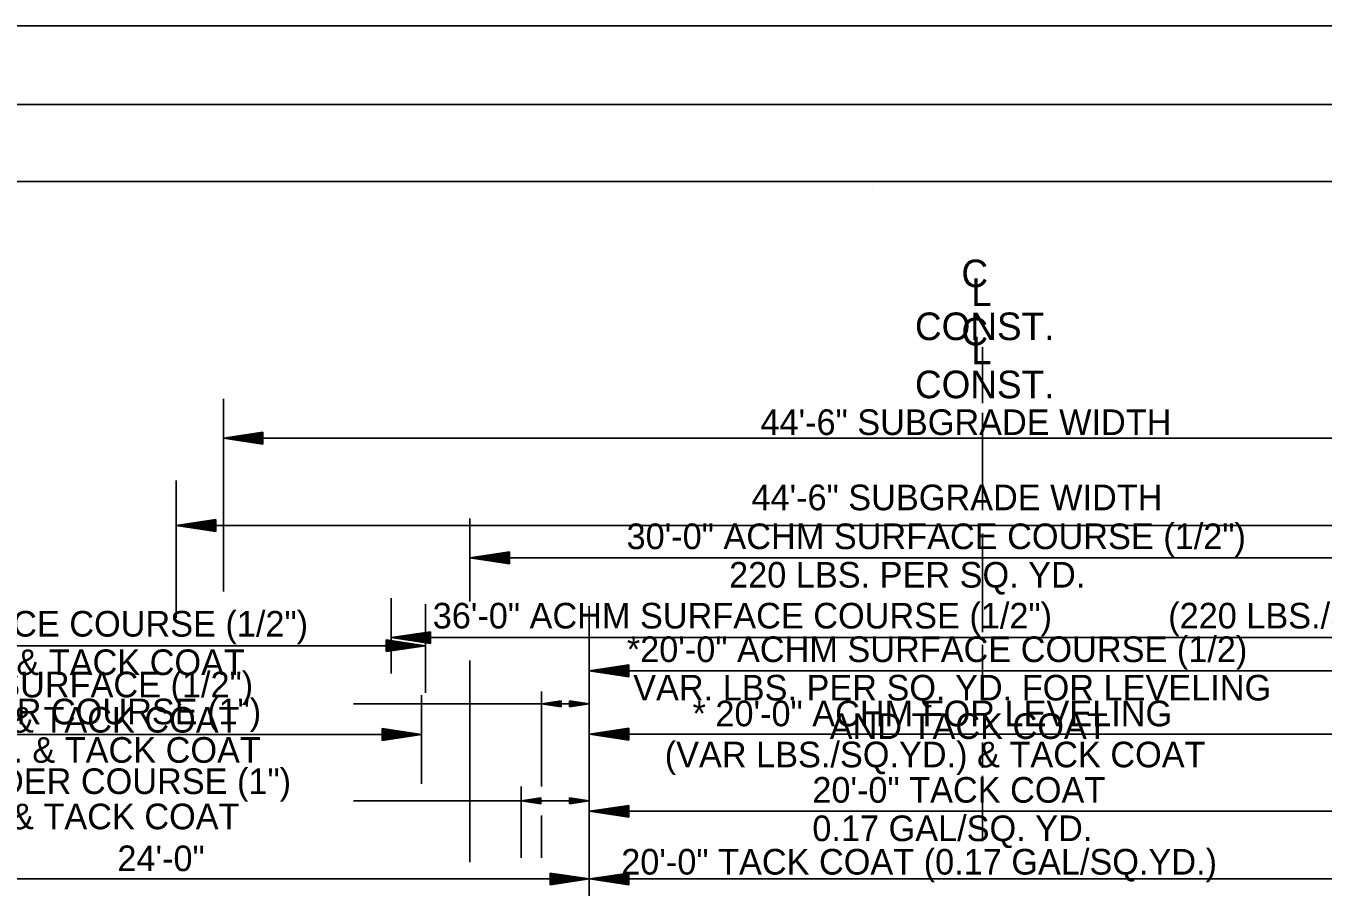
# Model space of a CAD drawing. Extents: x 1373719 to 1374161, y 379835 to 380167.
# Drawn here: x 1373940.76 to 1373973.66, y 380119.8 to 380141.63 of the extents above; entities that cross this region are included whole.
import ezdxf

# ---------------------------------------------------------------- set-up
doc = ezdxf.new("R2010")
doc.units = 0
for name, color, linetype in [('CL Construction', 7, 'Continuous'), ('DATE', 7, 'Continuous'), ('GREEN_TXT', 7, 'Continuous'), ('R_NoPlot', 7, 'Continuous'), ('Text 1', 7, 'Continuous')]:
    doc.layers.add(name, color=color, linetype=linetype)

msp = doc.modelspace()

# ---------------------------------------------------------------- linework, layer by layer
at = {"layer": 'CL Construction'}
for p, q in [((1373965.018, 380130.103), (1373965.018, 380131.819)), ((1373965.018, 380127.222), (1373965.018, 380128.764)), ((1373965.018, 380124.762), (1373965.018, 380125.938)), ((1373965.018, 380120.955), (1373965.018, 380122.619))]:
    msp.add_line(p, q, dxfattribs=at)
at = {"layer": 'DATE'}
for p, q in [((1374046.363, 380141.63), (1373870.363, 380141.63)), ((1373885.973, 380137.69), (1374044.063, 380137.69)), ((1373962.233, 380137.56), (1373962.233, 380137.56)), ((1373962.233, 380137.56), (1373962.233, 380137.56))]:
    msp.add_line(p, q, dxfattribs=at)
at = {"layer": 'GREEN_TXT'}
for p, q in [((1373944.572, 380130.103), (1373944.572, 380126.626)), ((1373945.572, 380129.112), (1373944.572, 380128.962)), ((1373985.467, 380128.962), (1373944.572, 380128.962)), ((1373945.572, 380128.812), (1373944.572, 380128.962)), ((1373945.572, 380129.087), (1373944.739, 380128.962)), ((1373945.572, 380128.837), (1373944.739, 380128.962)), ((1373945.572, 380129.062), (1373944.911, 380128.962)), ((1373945.572, 380128.863), (1373944.911, 380128.962)), ((1373945.572, 380129.037), (1373945.078, 380128.962)), ((1373945.572, 380128.888), (1373945.078, 380128.962)), ((1373945.572, 380129.011), (1373945.247, 380128.962)), ((1373945.572, 380128.914), (1373945.247, 380128.962)), ((1373945.572, 380128.986), (1373945.414, 380128.962)), ((1373945.572, 380128.939), (1373945.414, 380128.962)), ((1373945.572, 380128.812), (1373945.572, 380129.112)), ((1373950.02, 380127.121), (1373950.02, 380125.214)), ((1373951.02, 380126.271), (1373950.02, 380126.121)), ((1373951.02, 380126.246), (1373950.187, 380126.121)), ((1373951.02, 380126.22), (1373950.359, 380126.121)), ((1373951.02, 380126.195), (1373950.525, 380126.121)), ((1373951.02, 380126.17), (1373950.695, 380126.121)), ((1373951.02, 380125.971), (1373951.02, 380126.271)), ((1373980.02, 380126.121), (1373950.02, 380126.121)), ((1373951.02, 380125.971), (1373950.02, 380126.121)), ((1373951.02, 380125.996), (1373950.187, 380126.121)), ((1373951.02, 380126.021), (1373950.359, 380126.121)), ((1373951.02, 380126.046), (1373950.525, 380126.121)), ((1373951.02, 380126.072), (1373950.695, 380126.121)), ((1373951.02, 380126.144), (1373950.862, 380126.121)), ((1373951.02, 380126.097), (1373950.862, 380126.121)), ((1373953.833, 380122.346), (1373953.833, 380124.751)), ((1373954.333, 380124.517), (1373953.833, 380124.442)), ((1373954.333, 380124.367), (1373954.333, 380124.517)), ((1373954.544, 380124.517), (1373955.044, 380124.442)), ((1373954.544, 380124.517), (1373954.544, 380124.367)), ((1373955.044, 380122.166), (1373955.044, 380124.751)), ((1373953.833, 380124.442), (1373955.044, 380124.442)), ((1373954.333, 380124.367), (1373953.833, 380124.442)), ((1373954.333, 380124.504), (1373953.917, 380124.442)), ((1373954.333, 380124.379), (1373953.917, 380124.442)), ((1373954.333, 380124.491), (1373954.003, 380124.442)), ((1373954.333, 380124.392), (1373954.003, 380124.442)), ((1373954.333, 380124.479), (1373954.086, 380124.442)), ((1373954.333, 380124.404), (1373954.086, 380124.442)), ((1373954.333, 380124.466), (1373954.171, 380124.442)), ((1373954.333, 380124.417), (1373954.171, 380124.442)), ((1373954.333, 380124.453), (1373954.254, 380124.442)), ((1373954.333, 380124.43), (1373954.254, 380124.442)), ((1373954.544, 380124.504), (1373954.961, 380124.442)), ((1373954.544, 380124.491), (1373954.875, 380124.442)), ((1373954.544, 380124.479), (1373954.792, 380124.442)), ((1373954.544, 380124.466), (1373954.707, 380124.442)), ((1373954.544, 380124.453), (1373954.623, 380124.442)), ((1373954.544, 380124.367), (1373955.044, 380124.442)), ((1373954.544, 380124.417), (1373954.707, 380124.442)), ((1373954.544, 380124.392), (1373954.875, 380124.442)), ((1373954.544, 380124.379), (1373954.961, 380124.442)), ((1373954.544, 380124.404), (1373954.792, 380124.442)), ((1373954.544, 380124.43), (1373954.623, 380124.442)), ((1373956.05, 380123.824), (1373955.05, 380123.674)), ((1373955.05, 380123.674), (1373975.044, 380123.674)), ((1373956.05, 380123.524), (1373955.05, 380123.674)), ((1373956.05, 380123.799), (1373955.217, 380123.674)), ((1373956.05, 380123.549), (1373955.217, 380123.674)), ((1373956.05, 380123.774), (1373955.389, 380123.674)), ((1373956.05, 380123.575), (1373955.389, 380123.674)), ((1373956.05, 380123.749), (1373955.556, 380123.674)), ((1373956.05, 380123.6), (1373955.556, 380123.674)), ((1373956.05, 380123.723), (1373955.725, 380123.674)), ((1373956.05, 380123.626), (1373955.725, 380123.674)), ((1373956.05, 380123.698), (1373955.892, 380123.674)), ((1373956.05, 380123.651), (1373955.892, 380123.674)), ((1373956.05, 380123.524), (1373956.05, 380123.824)), ((1373953.319, 380120.537), (1373953.319, 380122.346)), ((1373953.819, 380122.055), (1373953.319, 380121.98)), ((1373953.319, 380121.98), (1373955.044, 380121.98)), ((1373953.819, 380121.905), (1373953.319, 380121.98)), ((1373953.819, 380122.042), (1373953.402, 380121.98)), ((1373953.819, 380121.917), (1373953.402, 380121.98)), ((1373953.819, 380122.029), (1373953.488, 380121.98)), ((1373953.819, 380121.93), (1373953.488, 380121.98)), ((1373953.819, 380122.017), (1373953.572, 380121.98)), ((1373953.819, 380121.942), (1373953.572, 380121.98)), ((1373953.819, 380122.004), (1373953.656, 380121.98)), ((1373953.819, 380121.955), (1373953.656, 380121.98)), ((1373953.819, 380121.991), (1373953.74, 380121.98)), ((1373953.819, 380121.968), (1373953.74, 380121.98)), ((1373953.819, 380121.905), (1373953.819, 380122.055)), ((1373954.544, 380122.055), (1373955.044, 380121.98)), ((1373954.544, 380122.055), (1373954.544, 380121.905)), ((1373954.544, 380122.042), (1373954.961, 380121.98)), ((1373954.544, 380122.029), (1373954.875, 380121.98)), ((1373954.544, 380122.017), (1373954.792, 380121.98)), ((1373954.544, 380122.004), (1373954.707, 380121.98)), ((1373954.544, 380121.991), (1373954.623, 380121.98)), ((1373954.544, 380121.905), (1373955.044, 380121.98)), ((1373954.544, 380121.955), (1373954.707, 380121.98)), ((1373954.544, 380121.93), (1373954.875, 380121.98)), ((1373954.544, 380121.917), (1373954.961, 380121.98)), ((1373954.544, 380121.942), (1373954.792, 380121.98)), ((1373954.544, 380121.968), (1373954.623, 380121.98)), ((1373955.044, 380118.359), (1373955.044, 380122.166)), ((1373953.833, 380120.537), (1373953.833, 380121.61)), ((1373934.02, 380120.001), (1373955.05, 380120.001)), ((1373954.05, 380120.151), (1373955.05, 380120.001)), ((1373954.05, 380120.151), (1373954.05, 380119.851)), ((1373954.05, 380120.126), (1373954.883, 380120.001)), ((1373954.05, 380120.101), (1373954.711, 380120.001)), ((1373954.05, 380120.076), (1373954.545, 380120.001)), ((1373954.05, 380120.05), (1373954.375, 380120.001)), ((1373954.05, 380120.025), (1373954.208, 380120.001)), ((1373954.05, 380119.851), (1373955.05, 380120.001)), ((1373954.05, 380119.952), (1373954.375, 380120.001)), ((1373954.05, 380119.902), (1373954.711, 380120.001)), ((1373954.05, 380119.876), (1373954.883, 380120.001)), ((1373954.05, 380119.927), (1373954.545, 380120.001)), ((1373954.05, 380119.978), (1373954.208, 380120.001)), ((1373956.05, 380120.151), (1373955.05, 380120.001)), ((1373955.05, 380120.001), (1373975.044, 380120.001)), ((1373956.05, 380119.851), (1373955.05, 380120.001)), ((1373956.05, 380120.126), (1373955.217, 380120.001)), ((1373956.05, 380119.876), (1373955.217, 380120.001)), ((1373956.05, 380120.101), (1373955.389, 380120.001)), ((1373956.05, 380119.902), (1373955.389, 380120.001)), ((1373956.05, 380120.076), (1373955.556, 380120.001)), ((1373956.05, 380119.927), (1373955.556, 380120.001)), ((1373956.05, 380120.05), (1373955.725, 380120.001)), ((1373956.05, 380119.953), (1373955.725, 380120.001)), ((1373956.05, 380120.025), (1373955.892, 380120.001)), ((1373956.05, 380119.978), (1373955.892, 380120.001)), ((1373956.05, 380119.851), (1373956.05, 380120.151))]:
    msp.add_line(p, q, dxfattribs=at)
for points in [[(1373949.063, 380124.442), (1373953.833, 380124.442)], [(1373949.063, 380121.98), (1373953.319, 380121.98)]]:
    msp.add_lwpolyline(points, dxfattribs=at)
at = {"layer": 'R_NoPlot'}
msp.add_lwpolyline([(1373879.769, 380139.637), (1374046.439, 380139.637), (1374046.439, 380032.969), (1373879.769, 380032.969)], close=True, dxfattribs=at)
at = {"layer": 'Text 1'}
for p, q in [((1373965.018, 380132.064), (1373965.018, 380133.484)), ((1373945.768, 380127.292), (1373945.768, 380132.177)), ((1373946.768, 380131.327), (1373945.768, 380131.177)), ((1373945.768, 380131.177), (1373984.268, 380131.177)), ((1373946.768, 380131.027), (1373945.768, 380131.177)), ((1373946.768, 380131.302), (1373945.935, 380131.177)), ((1373946.768, 380131.052), (1373945.935, 380131.177)), ((1373946.768, 380131.276), (1373946.107, 380131.177)), ((1373946.768, 380131.077), (1373946.107, 380131.177)), ((1373946.768, 380131.251), (1373946.273, 380131.177)), ((1373946.768, 380131.102), (1373946.273, 380131.177)), ((1373946.768, 380131.226), (1373946.443, 380131.177)), ((1373946.768, 380131.128), (1373946.443, 380131.177)), ((1373946.768, 380131.2), (1373946.61, 380131.177)), ((1373946.768, 380131.153), (1373946.61, 380131.177)), ((1373946.768, 380131.027), (1373946.768, 380131.327)), ((1373965.018, 380129.348), (1373965.018, 380130.891)), ((1373952.02, 380129.144), (1373952.02, 380127.032)), ((1373953.018, 380128.294), (1373952.018, 380128.144)), ((1373953.018, 380127.994), (1373952.018, 380128.144)), ((1373952.02, 380128.144), (1373978.02, 380128.144)), ((1373953.018, 380128.269), (1373952.185, 380128.144)), ((1373953.018, 380128.019), (1373952.185, 380128.144)), ((1373953.018, 380128.244), (1373952.357, 380128.144)), ((1373953.018, 380128.045), (1373952.357, 380128.144)), ((1373953.018, 380128.219), (1373952.524, 380128.144)), ((1373953.018, 380128.07), (1373952.524, 380128.144)), ((1373953.018, 380128.193), (1373952.693, 380128.144)), ((1373953.018, 380128.096), (1373952.693, 380128.144)), ((1373953.018, 380128.168), (1373952.86, 380128.144)), ((1373953.018, 380128.121), (1373952.86, 380128.144)), ((1373953.018, 380127.994), (1373953.018, 380128.294)), ((1373965.018, 380126.962), (1373965.018, 380127.293)), ((1373950.895, 380124.718), (1373950.895, 380126.972)), ((1373955.044, 380118.358), (1373955.044, 380126.916)), ((1373965.018, 380126.259), (1373965.018, 380126.962)), ((1373950.895, 380125.916), (1373930.823, 380125.916)), ((1373949.895, 380126.066), (1373950.895, 380125.916)), ((1373949.895, 380126.066), (1373949.895, 380125.766)), ((1373949.895, 380126.041), (1373950.728, 380125.916)), ((1373949.895, 380126.015), (1373950.556, 380125.916)), ((1373949.895, 380125.99), (1373950.389, 380125.916)), ((1373949.895, 380125.964), (1373950.22, 380125.916)), ((1373949.895, 380125.939), (1373950.053, 380125.916)), ((1373949.895, 380125.766), (1373950.895, 380125.916)), ((1373949.895, 380125.867), (1373950.22, 380125.916)), ((1373949.895, 380125.816), (1373950.556, 380125.916)), ((1373949.895, 380125.791), (1373950.728, 380125.916)), ((1373949.895, 380125.841), (1373950.389, 380125.916)), ((1373949.895, 380125.892), (1373950.053, 380125.916)), ((1373952.02, 380125.538), (1373952.02, 380120.424)), ((1373956.046, 380125.429), (1373955.046, 380125.279)), ((1373956.046, 380125.129), (1373955.046, 380125.279)), ((1373955.046, 380125.279), (1373975.044, 380125.279)), ((1373956.046, 380125.404), (1373955.213, 380125.279)), ((1373956.046, 380125.154), (1373955.213, 380125.279)), ((1373956.046, 380125.378), (1373955.385, 380125.279)), ((1373956.046, 380125.179), (1373955.385, 380125.279)), ((1373956.046, 380125.353), (1373955.551, 380125.279)), ((1373956.046, 380125.204), (1373955.551, 380125.279)), ((1373956.046, 380125.328), (1373955.721, 380125.279)), ((1373956.046, 380125.23), (1373955.721, 380125.279)), ((1373956.046, 380125.302), (1373955.888, 380125.279)), ((1373956.046, 380125.255), (1373955.888, 380125.279)), ((1373956.046, 380125.129), (1373956.046, 380125.429)), ((1373950.79, 380122.412), (1373950.79, 380124.665)), ((1373950.79, 380123.665), (1373930.823, 380123.665)), ((1373949.79, 380123.815), (1373950.79, 380123.665)), ((1373949.79, 380123.815), (1373949.79, 380123.515)), ((1373949.79, 380123.79), (1373950.623, 380123.665)), ((1373949.79, 380123.765), (1373950.451, 380123.665)), ((1373949.79, 380123.74), (1373950.284, 380123.665)), ((1373949.79, 380123.714), (1373950.115, 380123.665)), ((1373949.79, 380123.689), (1373949.948, 380123.665)), ((1373949.79, 380123.515), (1373950.79, 380123.665)), ((1373949.79, 380123.616), (1373950.115, 380123.665)), ((1373949.79, 380123.566), (1373950.451, 380123.665)), ((1373949.79, 380123.54), (1373950.623, 380123.665)), ((1373949.79, 380123.591), (1373950.284, 380123.665)), ((1373949.79, 380123.642), (1373949.948, 380123.665)), ((1373965.018, 380122.821), (1373965.018, 380123.461)), ((1373975.044, 380121.718), (1373955.044, 380121.718)), ((1373956.048, 380121.866), (1373955.048, 380121.716)), ((1373956.048, 380121.566), (1373955.048, 380121.716)), ((1373956.048, 380121.841), (1373955.215, 380121.716)), ((1373956.048, 380121.591), (1373955.215, 380121.716)), ((1373956.048, 380121.816), (1373955.387, 380121.716)), ((1373956.048, 380121.617), (1373955.387, 380121.716)), ((1373956.048, 380121.791), (1373955.554, 380121.716)), ((1373956.048, 380121.642), (1373955.554, 380121.716)), ((1373956.048, 380121.765), (1373955.723, 380121.716)), ((1373956.048, 380121.668), (1373955.723, 380121.716)), ((1373956.048, 380121.74), (1373955.89, 380121.716)), ((1373956.048, 380121.693), (1373955.89, 380121.716)), ((1373956.048, 380121.566), (1373956.048, 380121.866))]:
    msp.add_line(p, q, dxfattribs=at)

# ---------------------------------------------------------------- texts
at = {"layer": 'CL Construction'}
for s, p in [('C', (1373964.484, 380133.531)), ('L', (1373964.731, 380133.054)), ('CONST.', (1373963.306, 380132.19))]:
    msp.add_text(s, height=0.7, dxfattribs=at).set_placement(p)
at = {"layer": 'GREEN_TXT'}
for s, p in [('44\'-6" SUBGRADE WIDTH', (1373959.159, 380129.35)), ('36\'-0" ACHM SURFACE COURSE (1/2") ', (1373951.075, 380126.352)), ('(220 LBS./SQ. YD.)', (1373969.728, 380126.352)), ('2\'-1 1/2" ACHM SURFACE (1/2")', (1373933.807, 380124.606)), ('* 20\'-0" ACHM FOR LEVELING', (1373957.665, 380123.872)), ('(220 LBS./SQ. YD.) & TACK COAT', (1373932.555, 380123.712)), ('(VAR LBS./SQ.YD.) & TACK COAT', (1373956.959, 380122.832)), ('2\'-2 3/4" ACHM BINDER COURSE (1")', (1373932.403, 380122.155)), ('(330 LBS./SQ. YD.) & TACK COAT', (1373932.554, 380121.261)), ('24\'-0"', (1373943.077, 380120.199)), ('20\'-0" TACK COAT (0.17 GAL/SQ.YD.)', (1373955.856, 380120.112))]:
    msp.add_text(s, height=0.65, dxfattribs=at).set_placement(p)
at = {"layer": 'Text 1'}
for s, height, p in [('C', 0.7, (1373964.484, 380135.006)), ('L', 0.7, (1373964.731, 380134.528)), ('CONST.', 0.7, (1373963.306, 380133.664)), ('44\'-6" SUBGRADE WIDTH', 0.65, (1373959.387, 380131.258)), ('30\'-0" ACHM SURFACE COURSE (1/2")', 0.65, (1373955.992, 380128.364)), ('220 LBS. PER SQ. YD.', 0.65, (1373958.592, 380127.389)), ('5\'-1 1/2" ACHM SURFACE COURSE (1/2")', 0.65, (1373931.24, 380126.146)), ('*20\'-0" ACHM SURFACE COURSE (1/2)', 0.65, (1373955.998, 380125.501)), ('220 LBS. PER SQ. YD. & TACK COAT', 0.65, (1373931.24, 380125.171)), ('VAR. LBS. PER SQ. YD. FOR LEVELING', 0.65, (1373956.159, 380124.526)), ('5\'-2 3/4" ACHM BINDER COURSE (1")', 0.65, (1373931.645, 380123.922)), ('AND TACK COAT', 0.65, (1373961.144, 380123.551)), ('330 LBS. PER SQ. YD. & TACK COAT', 0.65, (1373931.645, 380122.947)), ('20\'-0" TACK COAT', 0.65, (1373960.703, 380121.935)), ('0.17 GAL/SQ. YD.', 0.65, (1373960.703, 380120.96))]:
    msp.add_text(s, height=height, dxfattribs=at).set_placement(p)

doc.saveas('drawing.dxf')
